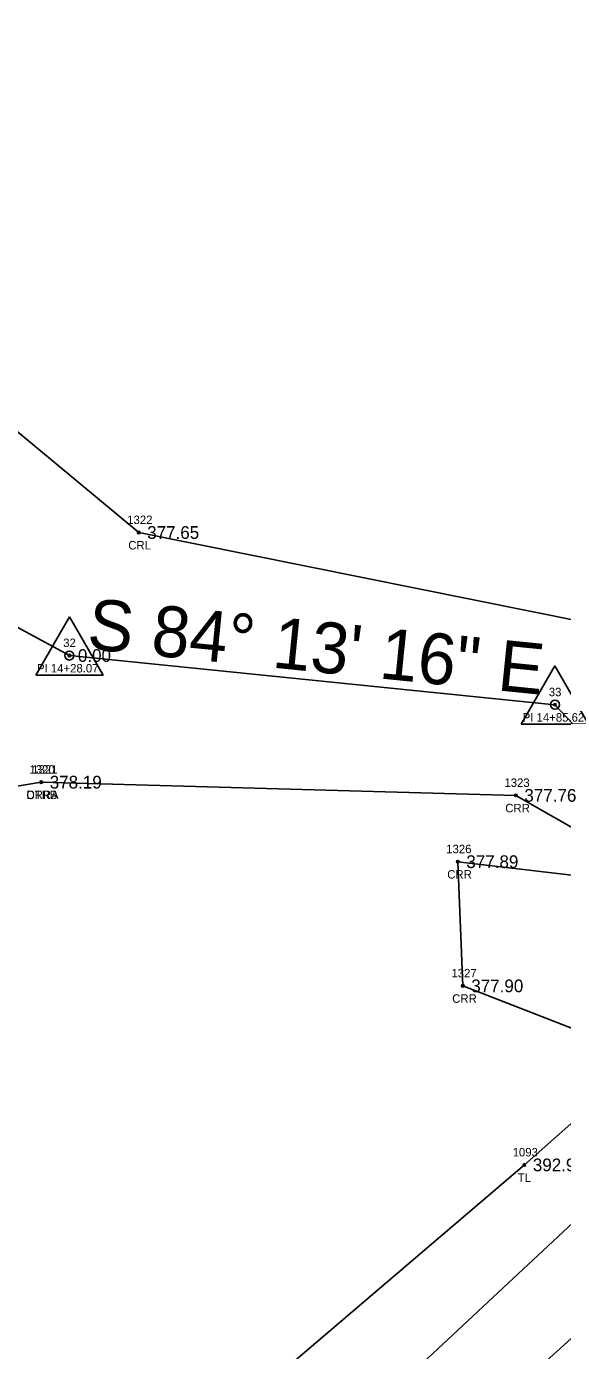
# Model space of a CAD drawing. Extents: x 2116015 to 2118228, y 979206 to 981145.
# Drawn here: x 2117252 to 2117315.2, y 980114.5 to 980270.7 of the extents above; entities that cross this region are included whole.
import ezdxf

# ---------------------------------------------------------------- set-up
doc = ezdxf.new("R2010")
doc.units = 0
for name, color, linetype in [('RD_EX_H2O', 7, 'Continuous'), ('RD_EX_H2O_txCode', 7, 'Continuous'), ('RD_EX_Road', 7, 'Continuous'), ('RD_EX_TX_H2O_ELEV', 7, 'Continuous'), ('RD_EX_TX_VEG_ELEV', 7, 'Continuous'), ('RD_EX_VEG', 7, 'Continuous'), ('RD_EX_VEG_txCode', 7, 'Continuous'), ('RD_HC_Cl', 7, 'Continuous'), ('RD_HC_Data', 7, 'Continuous'), ('RD_HC_Survey_ELEV', 7, 'Continuous'), ('RD_HC_txCode', 7, 'Continuous'), ('RD_SMD_Locator', 7, 'Continuous')]:
    doc.layers.add(name, color=color, linetype=linetype)

msp = doc.modelspace()

# ---------------------------------------------------------------- linework, layer by layer
at = {"layer": 'RD_EX_H2O'}
for points in [[(2117055.27, 980533.4), (2117084.87, 980468.5), (2117113.12, 980396.82), (2117150.26, 980360.48), (2117172.14, 980330.53), (2117167.4, 980300.56), (2117152, 980282.05), (2117153.33, 980268.31), (2117164.01, 980260.72), (2117221.6, 980247.26), (2117265.25, 980211.02), (2117324.27, 980199.15), (2117347.37, 980175.31), (2117365.85, 980182.55), (2117389.45, 980162.29), (2117399.63, 980142.01), (2117411.26, 980120.88), (2117420.42, 980068.64), (2117446.24, 980057.21), (2117497.11, 980045.39), (2117594.71, 979999.33), (2117646.33, 979985.56), (2117750.91, 980032.44), (2117805.09, 980018.87)], [(2117108.2, 980200.33), (2117119.12, 980172.91), (2117196.12, 980163.21), (2117213.19, 980174.82), (2117253.76, 980181.57)], [(2117253.76, 980181.57), (2117309.73, 980180.01), (2117328.75, 980169.13), (2117302.89, 980172.19), (2117303.47, 980157.54), (2117331.87, 980146.51), (2117356.54, 980132.72), (2117379.52, 980112.38), (2117402.94, 980061.78), (2117424.79, 980029.41), (2117490.12, 980015.27), (2117551.05, 979984.61)]]:
    msp.add_lwpolyline(points, dxfattribs=at)
at = {"layer": 'RD_EX_Road'}
msp.add_lwpolyline([(2116412.2, 979638.84), (2116468.17, 979651.36), (2116519.2, 979662.5), (2116617.24, 979678.85), (2116665.51, 979689.1), (2116714.23, 979702.46), (2116761.42, 979719.35), (2116806.99, 979737.42), (2116852.23, 979758.11), (2116896.57, 979780.91), (2116939.1, 979805.52), (2116978.46, 979832.1), (2117021.29, 979863.87), (2117058.15, 979895.61), (2117096.06, 979930.47), (2117170.14, 979995.71), (2117244.91, 980062.82), (2117320.63, 980133.49), (2117326.56, 980126.36)], dxfattribs=at)
at = {"layer": 'RD_EX_VEG'}
msp.add_lwpolyline([(2116712.02, 979710.38), (2116759.23, 979727.55), (2116802.24, 979746.7), (2116849.22, 979766.16), (2116893.59, 979788.48), (2116935.29, 979812.54), (2116975.95, 979836.39), (2117019.34, 979866.44), (2117054.55, 979897.64), (2117091.93, 979934.98), (2117160.1, 980005.89), (2117234.47, 980071.39), (2117310.73, 980136.42), (2117382.56, 980200.01), (2117453.09, 980281.19), (2117606.26, 980413.06), (2117681.92, 980479.39), (2117728.74, 980526.62), (2117785.53, 980582.83), (2117819.37, 980618.82)], dxfattribs=at)
at = {"layer": 'RD_HC_Cl'}
for p, q in [((2117075.77, 979898.29), (2117736.78, 980496.56)), ((2117154.31, 980252.06), (2117257.08, 980196.51)), ((2117257.08, 980196.51), (2117314.34, 980190.71)), ((2117314.34, 980190.71), (2117353.15, 980149.34))]:
    msp.add_line(p, q, dxfattribs=at)
at = {"layer": 'RD_HC_Data'}
for p, q in [((2117253.11, 980194.21), (2117257.08, 980201.09)), ((2117257.08, 980201.09), (2117261.05, 980194.21)), ((2117253.11, 980194.21), (2117261.05, 980194.21)), ((2117310.37, 980188.42), (2117314.34, 980195.3)), ((2117314.34, 980195.3), (2117318.31, 980188.42)), ((2117310.37, 980188.42), (2117318.31, 980188.42))]:
    msp.add_line(p, q, dxfattribs=at)
for centre in [(2117257.08, 980196.51), (2117314.34, 980190.71)]:
    msp.add_circle(centre, 0.529, dxfattribs=at)
at = {"layer": 'RD_SMD_Locator'}
for centre in [(2117265.25, 980211.02), (2117257.08, 980196.51), (2117314.34, 980190.71), (2117253.76, 980181.57), (2117253.76, 980181.57), (2117309.73, 980180.01), (2117302.89, 980172.19), (2117303.47, 980157.54), (2117310.73, 980136.42)]:
    msp.add_circle(centre, 0.15, dxfattribs=at)

# ---------------------------------------------------------------- texts
at = {"layer": 'RD_EX_H2O_txCode'}
for s, p in [('1322', (2117263.9, 980212.02)), ('CRL', (2117264.02, 980209.02)), ('1320', (2117252.38, 980182.57)), ('1321', (2117252.7, 980182.57)), ('1323', (2117308.38, 980181.01)), ('CRRA', (2117252.02, 980179.57)), ('DTRB', (2117252.02, 980179.57)), ('CRR', (2117308.48, 980178.01)), ('1326', (2117301.52, 980173.19)), ('CRR', (2117301.64, 980170.19)), ('1327', (2117302.13, 980158.54)), ('CRR', (2117302.22, 980155.54))]:
    msp.add_text(s, height=1, dxfattribs=at).set_placement(p)
at = {"layer": 'RD_EX_TX_H2O_ELEV'}
for s, p in [('377.65', (2117266.25, 980210.27)), ('378.19', (2117254.76, 980180.82)), ('378.19', (2117254.76, 980180.82)), ('377.76', (2117310.73, 980179.26)), ('377.89', (2117303.89, 980171.44)), ('377.90', (2117304.47, 980156.79))]:
    msp.add_text(s, height=1.5, dxfattribs=at).set_placement(p)
at = {"layer": 'RD_EX_TX_VEG_ELEV'}
msp.add_text('392.92', height=1.5, dxfattribs=at).set_placement((2117311.73, 980135.67))
at = {"layer": 'RD_EX_VEG_txCode'}
for s, p in [('1093', (2117309.35, 980137.42)), ('TL', (2117309.96, 980134.42))]:
    msp.add_text(s, height=1, dxfattribs=at).set_placement(p)
at = {"layer": 'RD_HC_Data'}
msp.add_text('S 84%%d 13\' 16" E', height=6, rotation=354.221, dxfattribs=at).set_placement((2117259.04, 980197.31))
at = {"layer": 'RD_HC_Survey_ELEV'}
msp.add_text('0.00', height=1.5, dxfattribs=at).set_placement((2117258.08, 980195.76))
at = {"layer": 'RD_HC_txCode'}
for s, p in [('32', (2117256.35, 980197.51)), ('PI 14+28.07', (2117253.26, 980194.51)), ('33', (2117313.61, 980191.71)), ('PI 14+85.62', (2117310.54, 980188.71))]:
    msp.add_text(s, height=1, dxfattribs=at).set_placement(p)

doc.saveas('drawing.dxf')
